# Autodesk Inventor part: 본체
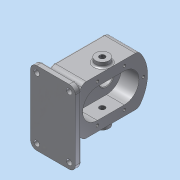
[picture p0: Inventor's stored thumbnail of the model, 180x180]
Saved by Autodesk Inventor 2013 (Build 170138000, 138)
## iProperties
Created: 2019-03
Part Number: 본체
Material: 알루미늄 6061
Document SubType Name: Modeling
Designer: Administrator
Mass: 1194.85 g
Surface Area: 724.416 cm^2
Volume: 440.905 cm^3
Density: 2.71 g/cm^3
Author: Administrator
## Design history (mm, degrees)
sketch "스케치1"
  geometry: L1 (26.5, -60)-(-26.5, -60); L2 (-36.5, -50)-(-36.5, 50); L3 (-26.5, 60)-(26.5, 60); L4 (36.5, 50)-(36.5, -50); A1 r 10 centre (26.5, -50) between (26.5, -60) and (36.5, -50); A2 r 10 centre (26.5, 50) between (36.5, 50) and (26.5, 60); A3 r 10 centre (-26.5, 50) between (-26.5, 60) and (-36.5, 50); A4 r 10 centre (-26.5, -50) between (-36.5, -50) and (-26.5, -60); 6 further points
  constraints: 8 end point, 8 point on circle, 8 tangent, 6 point on line, 4 centre point, 3 equal radius, 2 midpoint, 2 parallel, 1 horizontal, 1 horizontal alignment, 1 perpendicular, 1 vertical alignment
  dimensions: "d0" = 73 distance of point (-36.5, 60) point (36.5, 60); "d1" = 120 distance of point (-36.5, -60) point (-36.5, 60); "d2" = 10 radius of A1
extrude "돌출1" new body sketch "스케치1" distance "d4" = 10; taper "d5" = 0 deg
hole "구멍1" diameter "d8" = 9; stored, may be unused: countersink angle "d12" = 90 deg, drill point angle "d14" = 118 deg; dims "d6" = 10, "d7" = 10, "d9" = 6, "d10" = 4, "d11" = 2, "d13" = 8
hole "구멍2" diameter "d17" = 9; stored, may be unused: countersink angle "d21" = 90 deg, drill point angle "d23" = 118 deg; dims "d15" = 10, "d16" = 10, "d18" = 6, "d19" = 4, "d20" = 2, "d22" = 8
sketch "스케치2"
  geometry: L1 (36.5, -50)-(36.5, 50) reference; 2 further points
  constraints: 1 horizontal alignment, 1 other
  dimensions: "d24" = 10 distance from line of L1 point (26.5, 0)
feature "엠보싱1" sketch "스케치2" dims "d0" = 73, "d1" = 120, "d2" = 10, "d18" = 6, "d25" = 0.5, "d26" = 0
sketch "스케치3"
  geometry: L1 (24.115, 10.5)-(24.529, 10.5) reference; L2 (24.529, 10.5)-(24.529, 10) reference; L3 (24.529, 10)-(36.5, 10) reference; L4 (36.5, 10)-(36.5, 0) reference; L5 (36.5, 0)-(-36.5, 0) reference; L6 (-36.5, 0)-(-36.5, 10) reference; L7 (-36.5, 10)-(24.115, 10) reference; L8 (24.115, 10)-(24.115, 10.5) reference; L9 (-36.5, 10)-(6.5, 10); L10 (6.5, 10)-(6.5, 25); L11 (6.5, 25)-(-36.5, 25); L12 (-36.5, 25)-(-36.5, 10); 1 further point
  constraints: 8 end point, 2 parallel, 1 horizontal, 1 perpendicular
  dimensions: "d27" = 43 distance of L11.end L10.end; "d42" = 15 distance of L9.end L10.end
extrude "돌출2" join sketch "스케치3" distance "d28" = 6; taper "d30" = 0 deg; dims "d29" = 6, "d31" = 0
fillet "모깎기1" dims "d32" = 6
fillet "모깎기2" dims "d33" = 3
sketch "스케치4"
  geometry: L1 (0, 0)-(100, 0) reference; L2 (44, 25)-(56, 25) reference; L3 (90, 118)-(90, 38); L4 (10, 38)-(10, 118); A1 r 60 centre (50, 78) between (86, 126) and (14, 126); A2 r 10 centre (20, 118) between (14, 126) and (10, 118); A3 r 10 centre (80, 118) between (90, 118) and (86, 126); A4 r 10 centre (20, 38) between (10, 38) and (14, 30); A5 r 60 centre (50, 78) between (14, 30) and (86, 30); A6 r 10 centre (80, 38) between (86, 30) and (90, 38); 6 further points
  constraints: 14 point on circle, 6 centre point, 4 end point, 4 tangent, 2 midpoint, 1 coincident, 1 equal radius, 1 parallel
  dimensions: "d36" = 120 diameter of A1; "d37" = 10 radius of A2; "d144" = 78 distance of point (50, 0) A1.centre
extrude "돌출3" join sketch "스케치4" distance "d40" = 53; taper "d41" = 0 deg
fillet "모깎기3" dims "d43" = 3
fillet "모깎기4" dims "d44" = 3
sketch "스케치5"
  geometry: L1 (-26, 100)-(-26, 56); L2 (-74, 56)-(-74, 100); L3 (-100, 0)-(0, 0) reference; A1 r 24 centre (-50, 100) between (-26, 100) and (-74, 100); A2 r 24 centre (-50, 56) between (-74, 56) and (-26, 56); A3 r 60 centre (-50, 78) between (-86, 30) and (-14, 30) reference; 4 further points
  constraints: 4 end point, 4 point on circle, 3 midpoint, 2 centre point, 1 parallel, 1 vertical alignment
  dimensions: "d47" = 44 distance of L1.end L1.start; "d48" = 24 radius of A1; "d49" = 24 radius of A2; "d51" = 48 distance between parallel lines of L1 L2; "d92" = 22 distance of A1.centre A3.centre
extrude "돌출4" cut sketch "스케치5" distance "d54" = 29; taper "d55" = 0 deg
hole "구멍3" sketch "스케치3" diameter "d59" = 25; stored, may be unused: countersink angle "d63" = 90 deg, drill point angle "d65" = 0 deg; dims "d27" = 43, "d42" = 15, "d57" = 10, "d58" = 10, "d60" = 6, "d61" = 4, "d62" = 2, "d64" = 15
hole "구멍4" diameter "d68" = 25; stored, may be unused: countersink angle "d72" = 90 deg, drill point angle "d74" = 0 deg; dims "d66" = 10, "d67" = 10, "d69" = 6, "d70" = 4, "d71" = 2, "d73" = 15
chamfer "모따기1" distance "d75" = 1; stored, may be unused: second distance "d76" = 2, angle "d77" = 45 deg
sketch "스케치6"
  geometry: L1 (-10, 38)-(-10, 118) reference; L2 (-50, 100)-(-81, 100); A1 r 24 centre (-50, 100) between (-26, 100) and (-74, 100) reference; 1 further point
  constraints: 2 end point, 1 coincident, 1 perpendicular
hole "구멍5" sketch "스케치6" at (-81, 100) diameter "d80" = 4.459; stored, may be unused: countersink angle "d84" = 90 deg, drill point angle "d86" = 118 deg; dims "d81" = 10, "d82" = 4, "d83" = 2, "d85" = 12
sketch "스케치8"
  geometry: L1 (-10, 38)-(-10, 118) reference; L2 (-50, 56)-(-81, 56); A1 r 24 centre (-50, 56) between (-74, 56) and (-26, 56) reference; 1 further point
  constraints: 2 end point, 1 perpendicular
  dimensions: "d95" = 31 distance of L2.start L2.end
hole "구멍6" sketch "스케치8" at (-81, 56) diameter "d96" = 4.459; stored, may be unused: countersink angle "d100" = 90 deg, drill point angle "d102" = 118 deg; dims "d97" = 10, "d98" = 4, "d99" = 2, "d101" = 12
sketch "스케치9"
  geometry: L1 (50, 78)-(72, 78); C1 r 19 at (50, 100); A1 r 57 centre (50, 78) between (15.8, 32.4) and (41.857, 21.585) reference; 1 further point
  constraints: 2 end point, 1 centre point, 1 horizontal
  dimensions: "d108" = 38 diameter of C1; "d145" = 100 distance of point (50, 0) C1.centre
extrude "돌출5" join sketch "스케치9" distance "d109" = 17; taper "d110" = 0 deg
fillet "모깎기5" dims "d111" = 3
hole "구멍7" diameter "d114" = 17; stored, may be unused: countersink angle "d118" = 90 deg, drill point angle "d120" = 0 deg; dims "d112" = 10, "d113" = 10, "d115" = 10, "d116" = 28, "d117" = 7.3, "d119" = 26
chamfer "모따기2" distance "d121" = 0.7; stored, may be unused: second distance "d122" = 2, angle "d123" = 30 deg
fillet "모깎기6" dims "d124" = 0.5
sketch "스케치11"
  geometry: L1 (-43, -38)-(10, -38) reference; L2 (0, 80)-(0, 0) reference; L3 (-50, 0)-(0, 0) reference; L4 (20, -31)-(20, -38) reference; L5 (20, -38)-(-53, -38) reference; L6 (-53, -38)-(-53, -31) reference; L7 (-50, -28)-(17, -28) reference; L8 (-50, 0)-(-50, 80) reference; L9 (-50, 80)-(0, 80) reference; L10 (0, 80)-(0, 0) reference; L11 (-50, 0)-(0, 0) reference; L12 (0, 64.229)-(0, 59.77) reference; C1 r 11 at (-14, 40); A1 r 3 centre (17, -31) between (20, -31) and (17, -28) reference; A2 r 3 centre (-50, -31) between (-50, -28) and (-53, -31) reference; 1 further point
  constraints: 1 centre point
  dimensions: "d125" = 22 diameter of C1; "d131" = 14 distance from line of L2 C1.centre; "d142" = 40 distance from line of L3 C1.centre
extrude "돌출6" join sketch "스케치11" distance "d128" = 8; taper "d129" = 0 deg
fillet "모깎기7" dims "d130" = 3
hole "구멍8" diameter "d134" = 8.917; stored, may be unused: countersink angle "d138" = 90 deg, drill point angle "d140" = 118 deg; dims "d132" = 10, "d133" = 10, "d135" = 10, "d136" = 28, "d137" = 7.3, "d139" = 26
fillet "모깎기8" dims "d141" = 3
node "솔리드1"
mirror "대칭1"
pattern_circular "원형 패턴1" dims angle "d88" = 180 deg
pattern_circular "원형 패턴2" dims angle "d104" = -180 deg
mirror "대칭3"
node "절단 모서리 투영1"
node "절단 모서리 투영2"
